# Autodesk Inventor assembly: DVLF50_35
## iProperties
Created: 2010-03
Part Number: DVLF50_35
Document SubType Name: Assembly
Designer: TB
Mass: 831.695 g
Surface Area: 1569.84 cm^2
Volume: 831.695 cm^3
Density: 1 g/cm^3
Description: KM DVLF 50/35 - 100 mm
Slaglengde: 100.000 mm
Author: TB
